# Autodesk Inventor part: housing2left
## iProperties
Created: 2010-11
Part Number: housing2left
Document SubType Name: Modeling
Designer: ROBERT
Density: 1 g/cm^3
Author: ROBERT
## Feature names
1. TaggingFeature1
